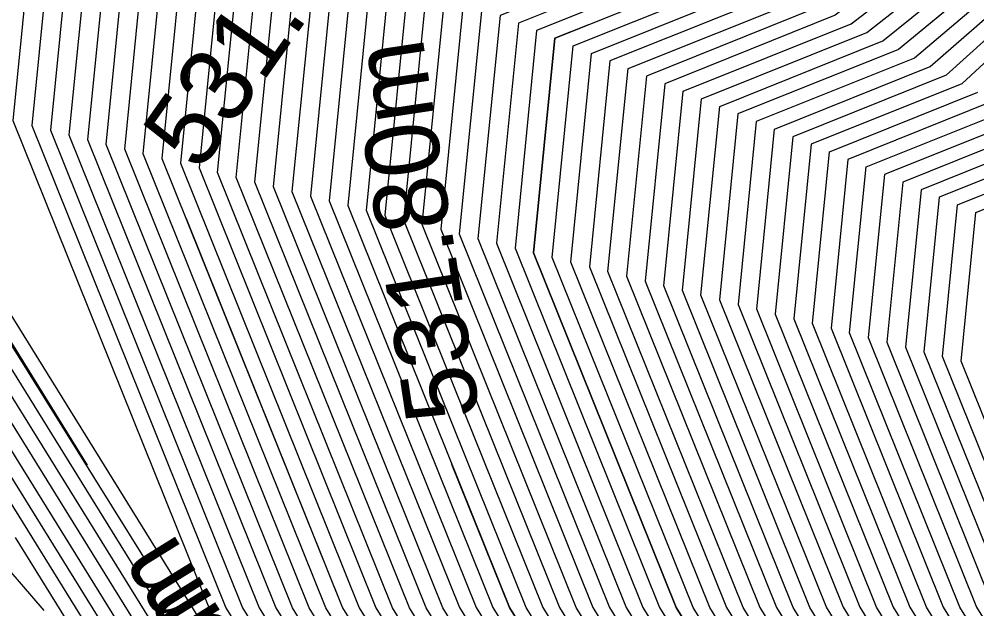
# Model space of a CAD drawing. Extents: x -866683 to -866410, y -1041951 to -1040252.
# Drawn here: x -866453.011 to -866449.115, y -1041913.65 to -1041911.251 of the extents above; entities that cross this region are included whole.
import ezdxf

# ---------------------------------------------------------------- set-up
doc = ezdxf.new("R2010")
doc.units = 0
for name, color, linetype in [('V-HL', 7, 'Continuous'), ('V-POPIS', 7, 'Continuous'), ('V-VEDL', 7, 'Continuous'), ('V_po_cm', 7, 'Continuous')]:
    doc.layers.add(name, color=color, linetype=linetype)

msp = doc.modelspace()

# ---------------------------------------------------------------- linework, layer by layer
at = {"layer": 'V-HL'}
msp.add_lwpolyline([(-866454.1336, -1041910.9392), (-866453.9375, -1041911.167), (-866453.3211, -1041912.1323), (-866452.4979, -1041913.4504)], dxfattribs=at)
at = {"layer": 'V-VEDL'}
for points in [[(-866449.345, -1041907.5366), (-866448.9556, -1041907.8532), (-866448.4862, -1041908.0339), (-866448.3105, -1041908.3809), (-866448.4285, -1041908.8942), (-866448.8402, -1041909.5738), (-866449.0019, -1041910.1655), (-866448.9134, -1041910.6692), (-866448.5749, -1041911.085), (-866448.5335, -1041911.4362), (-866448.7893, -1041911.7228), (-866449.3421, -1041911.9448), (-866449.4057, -1041912.585), (-866448.98, -1041913.6435), (-866448.0652, -1041915.1203), (-866447.345, -1041916.0757), (-866446.8195, -1041916.5099), (-866446.4887, -1041916.4228), (-866444.7099, -1041917.3864), (-866441.483, -1041919.4008), (-866432.1333, -1041925.5308)], [(-866449.0899, -1041915.6585), (-866450.3375, -1041913.6448), (-866450.9179, -1041912.2014), (-866450.8312, -1041911.3283), (-866450.0774, -1041911.0256), (-866449.6433, -1041910.7396), (-866449.529, -1041910.4704), (-866449.7345, -1041910.218), (-866449.7882, -1041909.9122), (-866449.69, -1041909.5531), (-866449.4401, -1041909.1405), (-866449.4048, -1041908.8149), (-866449.584, -1041908.5763), (-866449.9779, -1041908.4247), (-866450.6093, -1041908.3298), (-866451.4782, -1041908.2917), (-866452.5847, -1041908.3103), (-866453.3252, -1041908.3136), (-866453.6997, -1041908.3014), (-866453.7167, -1041908.2462)], [(-866452.8806, -1041908.7157), (-866451.3442, -1041908.6899), (-866450.7433, -1041908.7154), (-866450.3097, -1041908.7795), (-866450.0432, -1041908.882), (-866449.922, -1041909.0434), (-866449.9459, -1041909.2636), (-866450.1149, -1041909.5427), (-866450.1813, -1041909.7856), (-866450.145, -1041909.9925), (-866450.006, -1041910.1632), (-866450.1981, -1041910.3914), (-866450.7214, -1041910.677), (-866451.5758, -1041911.0201), (-866451.6741, -1041912.0096), (-866451.0162, -1041913.6454), (-866449.6023, -1041915.9277), (-866448.4893, -1041917.4043)], [(-866451.9822, -1041909.101), (-866451.181, -1041909.0875), (-866450.8676, -1041909.1009), (-866450.6414, -1041909.1343), (-866450.5025, -1041909.1878), (-866450.4392, -1041909.2719), (-866450.4517, -1041909.3868), (-866450.5399, -1041909.5323), (-866450.5745, -1041909.659), (-866450.5555, -1041909.7669), (-866450.483, -1041909.8559), (-866450.753, -1041910.0431), (-866451.3654, -1041910.3284), (-866452.3203, -1041910.7119), (-866452.4302, -1041911.8178), (-866451.695, -1041913.6461), (-866450.1147, -1041916.1968), (-866448.8707, -1041917.8472)], [(-866449.0884, -1041911.0879), (-866449.4333, -1041911.3742), (-866450.0867, -1041911.6366), (-866450.1618, -1041912.3932), (-866449.6588, -1041913.6442), (-866448.5775, -1041915.3894)]]:
    msp.add_lwpolyline(points, dxfattribs=at)
at = {"layer": 'V_po_cm'}
for points in [[(-866463.5642, -1041907.1206), (-866462.1303, -1041908.0993), (-866460.0158, -1041909.9324), (-866458.3918, -1041911.0851), (-866457.2584, -1041911.5573), (-866456.6155, -1041911.3489), (-866456.0661, -1041911.2348), (-866455.6103, -1041911.2147), (-866455.248, -1041911.2888), (-866454.787, -1041911.5932), (-866454.2273, -1041912.1278), (-866452.9104, -1041913.6573)], [(-866450.2492, -1041908.0307), (-866449.3085, -1041908.3929), (-866449.0944, -1041908.6778), (-866449.1366, -1041909.0666), (-866449.4351, -1041909.5593), (-866449.5523, -1041909.9882), (-866449.4882, -1041910.3534), (-866449.2428, -1041910.6548), (-866449.3104, -1041910.9486), (-866449.6909, -1041911.2348), (-866450.3845, -1041911.5133), (-866450.4643, -1041912.3165), (-866449.9303, -1041913.6444), (-866448.7825, -1041915.4971)], [(-866450.2696, -1041908.0711), (-866449.3544, -1041908.4234), (-866449.1462, -1041908.7006), (-866449.1872, -1041909.0789), (-866449.4776, -1041909.5582), (-866449.5916, -1041909.9755), (-866449.5292, -1041910.3308), (-866449.2905, -1041910.6241), (-866449.3658, -1041910.9138), (-866449.7553, -1041911.1999), (-866450.4589, -1041911.4824), (-866450.5399, -1041912.2973), (-866449.9981, -1041913.6445), (-866448.8337, -1041915.524)], [(-866448.885, -1041915.5509), (-866450.066, -1041913.6445), (-866450.6155, -1041912.2781), (-866450.5334, -1041911.4516), (-866449.8197, -1041911.165), (-866449.4213, -1041910.8789), (-866449.3382, -1041910.5934), (-866449.5703, -1041910.3083), (-866449.6309, -1041909.9629), (-866449.5201, -1041909.5572), (-866449.2378, -1041909.0912), (-866449.1979, -1041908.7235), (-866449.4004, -1041908.454), (-866450.2901, -1041908.1115)], [(-866450.3105, -1041908.1519), (-866449.4463, -1041908.4846), (-866449.2496, -1041908.7463), (-866449.2884, -1041909.1035), (-866449.5626, -1041909.5562), (-866449.6702, -1041909.9502), (-866449.6113, -1041910.2857), (-866449.3859, -1041910.5626), (-866449.4768, -1041910.8441), (-866449.8841, -1041911.1302), (-866450.6078, -1041911.4208), (-866450.6911, -1041912.2589), (-866450.1339, -1041913.6446), (-866448.9362, -1041915.5778)], [(-866448.9875, -1041915.6047), (-866450.2018, -1041913.6447), (-866450.7667, -1041912.2398), (-866450.6823, -1041911.39), (-866449.9485, -1041911.0953), (-866449.5323, -1041910.8093), (-866449.4336, -1041910.5319), (-866449.6524, -1041910.2631), (-866449.7095, -1041909.9376), (-866449.6051, -1041909.5551), (-866449.3389, -1041909.1159), (-866449.3013, -1041908.7692), (-866449.4922, -1041908.5151), (-866450.3309, -1041908.1923)], [(-866449.0387, -1041915.6316), (-866450.2696, -1041913.6447), (-866450.8423, -1041912.2206), (-866450.7568, -1041911.3592), (-866450.0129, -1041911.0605), (-866449.5878, -1041910.7745), (-866449.4813, -1041910.5012), (-866449.6934, -1041910.2406), (-866449.7489, -1041909.9249), (-866449.6476, -1041909.5541), (-866449.3895, -1041909.1282), (-866449.353, -1041908.792), (-866449.5381, -1041908.5457), (-866450.3514, -1041908.2327)], [(-866450.3922, -1041908.3134), (-866449.63, -1041908.6069), (-866449.4565, -1041908.8378), (-866449.4907, -1041909.1528), (-866449.7325, -1041909.552), (-866449.8275, -1041909.8996), (-866449.7755, -1041910.1955), (-866449.5767, -1041910.4397), (-866449.6988, -1041910.7048), (-866450.1418, -1041910.9907), (-866450.9057, -1041911.2975), (-866450.9935, -1041912.1822), (-866450.4054, -1041913.6449), (-866449.1412, -1041915.6855), (-866448.146, -1041917.0057)], [(-866450.4126, -1041908.3538), (-866449.6759, -1041908.6374), (-866449.5082, -1041908.8606), (-866449.5413, -1041909.1651), (-866449.775, -1041909.551), (-866449.8668, -1041909.8869), (-866449.8166, -1041910.1729), (-866449.6244, -1041910.409), (-866449.7542, -1041910.67), (-866450.2062, -1041910.9559), (-866450.9801, -1041911.2667), (-866451.0692, -1041912.163), (-866450.4733, -1041913.6449), (-866449.1924, -1041915.7124), (-866448.1841, -1041917.05)], [(-866450.4331, -1041908.3942), (-866449.7218, -1041908.668), (-866449.5599, -1041908.8835), (-866449.5918, -1041909.1774), (-866449.8175, -1041909.5499), (-866449.9061, -1041909.8743), (-866449.8576, -1041910.1504), (-866449.6721, -1041910.3783), (-866449.8097, -1041910.6352), (-866450.2706, -1041910.921), (-866451.0546, -1041911.2359), (-866451.1448, -1041912.1439), (-866450.5411, -1041913.645), (-866449.2436, -1041915.7393), (-866448.2223, -1041917.0943)], [(-866450.4535, -1041908.4346), (-866449.7677, -1041908.6986), (-866449.6117, -1041908.9063), (-866449.6424, -1041909.1897), (-866449.86, -1041909.5489), (-866449.9454, -1041909.8616), (-866449.8987, -1041910.1278), (-866449.7198, -1041910.3475), (-866449.8652, -1041910.6003), (-866450.335, -1041910.8862), (-866451.129, -1041911.205), (-866451.2204, -1041912.1247), (-866450.609, -1041913.6451), (-866449.2949, -1041915.7662), (-866448.2604, -1041917.1386)], [(-866450.4739, -1041908.475), (-866449.8136, -1041908.7292), (-866449.6634, -1041908.9292), (-866449.693, -1041909.2021), (-866449.9025, -1041909.5479), (-866449.9847, -1041909.8489), (-866449.9397, -1041910.1052), (-866449.7675, -1041910.3168), (-866449.9207, -1041910.5655), (-866450.3994, -1041910.8513), (-866451.2035, -1041911.1742), (-866451.296, -1041912.1055), (-866450.6769, -1041913.6451), (-866449.3461, -1041915.7931), (-866448.2986, -1041917.1829)], [(-866448.3367, -1041917.2272), (-866449.3974, -1041915.82), (-866450.7447, -1041913.6452), (-866451.3716, -1041912.0863), (-866451.278, -1041911.1434), (-866450.4638, -1041910.8164), (-866449.9762, -1041910.5307), (-866449.8152, -1041910.2861), (-866449.9808, -1041910.0827), (-866450.0241, -1041909.8363), (-866449.945, -1041909.5468), (-866449.7436, -1041909.2144), (-866449.7151, -1041908.952), (-866449.8596, -1041908.7597), (-866450.4944, -1041908.5154)], [(-866450.5148, -1041908.5558), (-866449.9055, -1041908.7903), (-866449.7668, -1041908.9749), (-866449.7942, -1041909.2267), (-866449.9875, -1041909.5458), (-866450.0634, -1041909.8236), (-866450.0219, -1041910.0601), (-866449.8629, -1041910.2554), (-866450.0317, -1041910.4958), (-866450.5282, -1041910.7816), (-866451.3524, -1041911.1126), (-866451.4472, -1041912.0671), (-866450.8126, -1041913.6453), (-866449.4486, -1041915.8469), (-866448.3749, -1041917.2714)], [(-866450.5352, -1041908.5961), (-866449.9514, -1041908.8209), (-866449.8185, -1041908.9977), (-866449.8447, -1041909.239), (-866450.03, -1041909.5448), (-866450.1027, -1041909.8109), (-866450.0629, -1041910.0376), (-866449.9106, -1041910.2246), (-866450.0872, -1041910.461), (-866450.5926, -1041910.7467), (-866451.4269, -1041911.0818), (-866451.5228, -1041912.048), (-866450.8805, -1041913.6453), (-866449.4998, -1041915.8738), (-866448.413, -1041917.3157)], [(-866448.4512, -1041917.36), (-866449.5511, -1041915.9008), (-866450.9484, -1041913.6454), (-866451.5984, -1041912.0288), (-866451.5013, -1041911.0509), (-866450.657, -1041910.7119), (-866450.1427, -1041910.4262), (-866449.9583, -1041910.1939), (-866450.104, -1041910.015), (-866450.142, -1041909.7983), (-866450.0725, -1041909.5437), (-866449.8953, -1041909.2513), (-866449.8703, -1041909.0206), (-866449.9973, -1041908.8515), (-866450.5556, -1041908.6365)], [(-866450.5965, -1041908.7173), (-866450.0892, -1041908.9126), (-866449.9737, -1041909.0663), (-866449.9965, -1041909.2759), (-866450.1574, -1041909.5416), (-866450.2206, -1041909.773), (-866450.1861, -1041909.9699), (-866450.0537, -1041910.1325), (-866450.2536, -1041910.3565), (-866450.7858, -1041910.6422), (-866451.6502, -1041910.9893), (-866451.7497, -1041911.9904), (-866451.0841, -1041913.6455), (-866449.6536, -1041915.9546), (-866448.5274, -1041917.4486)], [(-866450.6169, -1041908.7577), (-866450.1351, -1041908.9432), (-866450.0254, -1041909.0891), (-866450.0471, -1041909.2883), (-866450.1999, -1041909.5406), (-866450.2599, -1041909.7603), (-866450.2271, -1041909.9473), (-866450.1014, -1041910.1017), (-866450.3091, -1041910.3217), (-866450.8502, -1041910.6073), (-866451.7247, -1041910.9585), (-866451.8253, -1041911.9712), (-866451.152, -1041913.6456), (-866449.7048, -1041915.9815), (-866448.5656, -1041917.4929)], [(-866450.6373, -1041908.7981), (-866450.181, -1041908.9737), (-866450.0772, -1041909.112), (-866450.0976, -1041909.3006), (-866450.2424, -1041909.5396), (-866450.2993, -1041909.7476), (-866450.2682, -1041909.9248), (-866450.1491, -1041910.071), (-866450.3646, -1041910.2869), (-866450.9146, -1041910.5724), (-866451.7991, -1041910.9276), (-866451.9009, -1041911.952), (-866451.2199, -1041913.6456), (-866449.756, -1041916.0084), (-866448.6037, -1041917.5372)], [(-866448.6419, -1041917.5814), (-866449.8073, -1041916.0353), (-866451.2877, -1041913.6457), (-866451.9765, -1041911.9329), (-866451.8736, -1041910.8968), (-866450.979, -1041910.5376), (-866450.4201, -1041910.2521), (-866450.1968, -1041910.0403), (-866450.3092, -1041909.9022), (-866450.3386, -1041909.735), (-866450.2849, -1041909.5385), (-866450.1482, -1041909.3129), (-866450.1289, -1041909.1348), (-866450.2269, -1041909.0043), (-866450.6578, -1041908.8385)], [(-866448.68, -1041917.6257), (-866449.8585, -1041916.0622), (-866451.3556, -1041913.6458), (-866452.0521, -1041911.9137), (-866451.9481, -1041910.866), (-866451.0434, -1041910.5027), (-866450.4756, -1041910.2172), (-866450.2445, -1041910.0096), (-866450.3503, -1041909.8797), (-866450.3779, -1041909.7223), (-866450.3274, -1041909.5375), (-866450.1988, -1041909.3252), (-866450.1806, -1041909.1577), (-866450.2729, -1041909.0349), (-866450.6782, -1041908.8788)], [(-866448.7182, -1041917.67), (-866449.9098, -1041916.0892), (-866451.4235, -1041913.6458), (-866452.1277, -1041911.8945), (-866452.0225, -1041910.8352), (-866451.1078, -1041910.4679), (-866450.5311, -1041910.1824), (-866450.2922, -1041909.9788), (-866450.3913, -1041909.8571), (-866450.4172, -1041909.7097), (-866450.3699, -1041909.5365), (-866450.2494, -1041909.3375), (-866450.2323, -1041909.1805), (-866450.3188, -1041909.0655), (-866450.6986, -1041908.9192)], [(-866448.7563, -1041917.7143), (-866449.961, -1041916.1161), (-866451.4914, -1041913.6459), (-866452.2033, -1041911.8753), (-866452.097, -1041910.8044), (-866451.1722, -1041910.433), (-866450.5866, -1041910.1476), (-866450.3399, -1041909.9481), (-866450.4324, -1041909.8346), (-866450.4565, -1041909.697), (-866450.4124, -1041909.5354), (-866450.2999, -1041909.3498), (-866450.2841, -1041909.2034), (-866450.3647, -1041909.096), (-866450.7191, -1041908.9596)], [(-866450.7395, -1041909), (-866450.4106, -1041909.1266), (-866450.3358, -1041909.2262), (-866450.3505, -1041909.3621), (-866450.4549, -1041909.5344), (-866450.4958, -1041909.6843), (-866450.4734, -1041909.812), (-866450.3876, -1041909.9174), (-866450.642, -1041910.1128), (-866451.2366, -1041910.3981), (-866452.1714, -1041910.7735), (-866452.279, -1041911.8561), (-866451.5592, -1041913.646), (-866450.0122, -1041916.143), (-866448.7945, -1041917.7586)], [(-866450.7599, -1041909.0404), (-866450.4565, -1041909.1572), (-866450.3875, -1041909.2491), (-866450.4011, -1041909.3745), (-866450.4974, -1041909.5333), (-866450.5352, -1041909.6717), (-866450.5145, -1041909.7894), (-866450.4353, -1041909.8866), (-866450.6975, -1041910.0779), (-866451.301, -1041910.3633), (-866452.2459, -1041910.7427), (-866452.3546, -1041911.837), (-866451.6271, -1041913.646), (-866450.0635, -1041916.1699), (-866448.8326, -1041917.8029)], [(-866448.68, -1041915.4432), (-866449.7945, -1041913.6443), (-866450.313, -1041912.3549), (-866450.2356, -1041911.5749), (-866449.5621, -1041911.3045), (-866449.1994, -1041911.0182), (-866449.1474, -1041910.7163), (-866449.4061, -1041910.3985), (-866449.4737, -1041910.0135), (-866449.3501, -1041909.5614), (-866449.0355, -1041909.042)], [(-866448.6288, -1041915.4163), (-866449.7266, -1041913.6442), (-866450.2374, -1041912.374), (-866450.1611, -1041911.6057), (-866449.4977, -1041911.3393), (-866449.1439, -1041911.0531), (-866449.0997, -1041910.747), (-866449.365, -1041910.4211), (-866449.4343, -1041910.0262), (-866449.3076, -1041909.5624), (-866448.9849, -1041909.0297)], [(-866448.7313, -1041915.4701), (-866449.8624, -1041913.6444), (-866450.3886, -1041912.3357), (-866450.31, -1041911.5441), (-866449.6265, -1041911.2696), (-866449.2549, -1041910.9834), (-866449.1951, -1041910.6855), (-866449.4471, -1041910.3759), (-866449.513, -1041910.0009), (-866449.3926, -1041909.5603), (-866449.086, -1041909.0543)], [(-866448.9089, -1041917.8914), (-866450.166, -1041916.2237), (-866451.7628, -1041913.6461), (-866452.5058, -1041911.7986), (-866452.3948, -1041910.6811), (-866451.4298, -1041910.2936), (-866450.8085, -1041910.0083), (-866450.5307, -1041909.8252), (-866450.5966, -1041909.7443), (-866450.6138, -1041909.6463), (-866450.5823, -1041909.5313), (-866450.5023, -1041909.3991), (-866450.4909, -1041909.2948), (-866450.5484, -1041909.2183), (-866450.8008, -1041909.1212)], [(-866448.947, -1041917.9357), (-866450.2172, -1041916.2506), (-866451.8307, -1041913.6462), (-866452.5814, -1041911.7794), (-866452.4693, -1041910.6502), (-866451.4943, -1041910.2587), (-866450.864, -1041909.9734), (-866450.5784, -1041909.7945), (-866450.6376, -1041909.7218), (-866450.6531, -1041909.6337), (-866450.6248, -1041909.5302), (-866450.5528, -1041909.4114), (-866450.5427, -1041909.3176), (-866450.5943, -1041909.2489), (-866450.8212, -1041909.1616)], [(-866448.9852, -1041917.98), (-866450.2684, -1041916.2776), (-866451.8986, -1041913.6463), (-866452.657, -1041911.7602), (-866452.5437, -1041910.6194), (-866451.5587, -1041910.2238), (-866450.9195, -1041909.9386), (-866450.6261, -1041909.7637), (-866450.6787, -1041909.6992), (-866450.6924, -1041909.621), (-866450.6673, -1041909.5292), (-866450.6034, -1041909.4237), (-866450.5944, -1041909.3405), (-866450.6402, -1041909.2795), (-866450.8416, -1041909.2019)], [(-866450.862, -1041909.2423), (-866450.6861, -1041909.31), (-866450.6461, -1041909.3633), (-866450.654, -1041909.436), (-866450.7098, -1041909.5282), (-866450.7317, -1041909.6084), (-866450.7197, -1041909.6766), (-866450.6739, -1041909.733), (-866450.975, -1041909.9038), (-866451.6231, -1041910.189), (-866452.6182, -1041910.5886), (-866452.7326, -1041911.7411), (-866451.9665, -1041913.6463), (-866450.3197, -1041916.3045), (-866449.0233, -1041918.0243)], [(-866450.8825, -1041909.2827), (-866450.7321, -1041909.3406), (-866450.6978, -1041909.3862), (-866450.7046, -1041909.4483), (-866450.7523, -1041909.5271), (-866450.771, -1041909.5957), (-866450.7608, -1041909.6541), (-866450.7216, -1041909.7023), (-866451.0304, -1041909.869), (-866451.6875, -1041910.1541), (-866452.6926, -1041910.5578), (-866452.8082, -1041911.7219), (-866452.0343, -1041913.6464), (-866450.3709, -1041916.3314), (-866449.0615, -1041918.0686)], [(-866450.9029, -1041909.3231), (-866450.778, -1041909.3712), (-866450.7496, -1041909.409), (-866450.7552, -1041909.4607), (-866450.7948, -1041909.5261), (-866450.8104, -1041909.583), (-866450.8018, -1041909.6315), (-866450.7693, -1041909.6716), (-866451.0859, -1041909.8341), (-866451.7519, -1041910.1193), (-866452.7671, -1041910.527), (-866452.8839, -1041911.7027), (-866452.1022, -1041913.6465), (-866450.4221, -1041916.3583), (-866449.0996, -1041918.1129)], [(-866450.9233, -1041909.3635), (-866450.8239, -1041909.4018), (-866450.8013, -1041909.4319), (-866450.8057, -1041909.473), (-866450.8373, -1041909.525), (-866450.8497, -1041909.5704), (-866450.8429, -1041909.609), (-866450.817, -1041909.6408), (-866451.1414, -1041909.7993), (-866451.8163, -1041910.0844), (-866452.8415, -1041910.4961), (-866452.9595, -1041911.6835), (-866452.1701, -1041913.6465), (-866450.4734, -1041916.3852), (-866449.1378, -1041918.1572), (-866448.1632, -1041918.9624)], [(-866448.1918, -1041919.0146), (-866449.1759, -1041918.2014), (-866450.5246, -1041916.4121), (-866452.238, -1041913.6466), (-866453.0351, -1041911.6643), (-866452.916, -1041910.4653), (-866451.8807, -1041910.0496), (-866451.1969, -1041909.7645), (-866450.8647, -1041909.6101), (-866450.8839, -1041909.5864), (-866450.889, -1041909.5577), (-866450.8798, -1041909.524), (-866450.8563, -1041909.4853), (-866450.853, -1041909.4547), (-866450.8698, -1041909.4323), (-866450.9438, -1041909.4039)], [(-866453.9556, -1041910.9838), (-866450.5491, -1041916.4822), (-866449.2051, -1041918.2601), (-866448.2204, -1041919.0667), (-866447.5949, -1041918.902), (-866445.7626, -1041919.7202), (-866442.7235, -1041921.5211), (-866438.4776, -1041924.3049), (-866435.6682, -1041926.3451), (-866434.2952, -1041927.6416), (-866434.3586, -1041928.1946), (-866434.3894, -1041928.6198), (-866434.3877, -1041928.9172), (-866434.3533, -1041929.0867), (-866434.5515, -1041929.5677), (-866434.9823, -1041930.3602), (-866436.3089, -1041932.5679)], [(-866449.0329, -1041911.1227), (-866449.3689, -1041911.409), (-866450.0122, -1041911.6674), (-866450.0862, -1041912.4124), (-866449.5909, -1041913.6441), (-866448.5263, -1041915.3625)], [(-866449.1897, -1041911.172), (-866449.4333, -1041911.3742), (-866450.0867, -1041911.6366), (-866450.1618, -1041912.3932), (-866449.6588, -1041913.6442), (-866449.1812, -1041914.4151)], [(-866448.4751, -1041915.3356), (-866449.523, -1041913.644), (-866450.0106, -1041912.4316), (-866449.9377, -1041911.6982), (-866449.3045, -1041911.4439), (-866448.9774, -1041911.1576)], [(-866448.9219, -1041911.1924), (-866449.2401, -1041911.4788), (-866449.8633, -1041911.729), (-866449.935, -1041912.4508), (-866449.4552, -1041913.644), (-866448.4238, -1041915.3087)], [(-866448.8665, -1041911.2272), (-866449.1757, -1041911.5136), (-866449.7888, -1041911.7598), (-866449.8594, -1041912.4699), (-866449.3873, -1041913.6439), (-866448.3726, -1041915.2817)], [(-866453.8394, -1041911.2809), (-866452.7335, -1041913.066)], [(-866450.6946, -1041911.2735), (-866450.8312, -1041911.3283), (-866450.9179, -1041912.2014), (-866450.3375, -1041913.6448), (-866449.6105, -1041914.8183)], [(-866448.5527, -1041911.274), (-866448.5335, -1041911.4362), (-866448.7893, -1041911.7228), (-866449.3421, -1041911.9448), (-866449.4057, -1041912.585), (-866448.98, -1041913.6435), (-866448.3706, -1041914.6272)], [(-866453.7233, -1041911.5779), (-866450.5178, -1041916.7519), (-866449.2368, -1041918.4207), (-866448.2776, -1041919.1711), (-866447.64, -1041919.0032), (-866445.8179, -1041919.8073), (-866442.8113, -1041921.5833), (-866438.6201, -1041924.3313), (-866435.8481, -1041926.3566), (-866434.4954, -1041927.6592), (-866434.5619, -1041928.2392), (-866434.5942, -1041928.6852), (-866434.5924, -1041928.9971), (-866434.5563, -1041929.175), (-866434.7642, -1041929.6795), (-866435.216, -1041930.5107), (-866436.6075, -1041932.8263)], [(-866448.3213, -1041915.2548), (-866449.3194, -1041913.6438), (-866449.7837, -1041912.4891), (-866449.7144, -1041911.7907), (-866449.1113, -1041911.5485)], [(-866449.0469, -1041911.5833), (-866449.6399, -1041911.8215), (-866449.7081, -1041912.5083), (-866449.2515, -1041913.6438), (-866448.2701, -1041915.2279)], [(-866448.2189, -1041915.201), (-866449.1837, -1041913.6437), (-866449.6325, -1041912.5275), (-866449.5655, -1041911.8523), (-866448.9825, -1041911.6182)], [(-866448.9181, -1041911.6531), (-866449.491, -1041911.8831), (-866449.5569, -1041912.5467), (-866449.1158, -1041913.6437), (-866448.1676, -1041915.1741)], [(-866448.8537, -1041911.6879), (-866449.4165, -1041911.914), (-866449.4813, -1041912.5658), (-866449.0479, -1041913.6436)], [(-866448.7249, -1041911.7576), (-866449.2676, -1041911.9756), (-866449.3301, -1041912.6042), (-866448.9122, -1041913.6435)], [(-866448.8443, -1041913.6434), (-866449.2545, -1041912.6234), (-866449.1932, -1041912.0064), (-866448.6604, -1041911.7925)], [(-866448.7764, -1041913.6433), (-866449.1788, -1041912.6426), (-866449.1187, -1041912.0372), (-866448.596, -1041911.8273)], [(-866453.6072, -1041911.875), (-866450.5022, -1041916.8868), (-866449.2527, -1041918.5009), (-866448.3062, -1041919.2233), (-866447.6626, -1041919.0538), (-866445.8456, -1041919.8509), (-866442.8552, -1041921.6144), (-866438.6913, -1041924.3444), (-866435.938, -1041926.3623), (-866434.5954, -1041927.668), (-866434.6635, -1041928.2615), (-866434.6966, -1041928.7179), (-866434.6947, -1041929.0371), (-866434.6578, -1041929.2191), (-866434.8706, -1041929.7354), (-866435.3329, -1041930.586), (-866436.7568, -1041932.9556)], [(-866452.3317, -1041912.0626), (-866451.695, -1041913.6461), (-866450.5156, -1041915.5497)], [(-866453.4911, -1041912.172), (-866450.4866, -1041917.0217), (-866449.2685, -1041918.5812), (-866448.3348, -1041919.2755), (-866447.6852, -1041919.1044), (-866445.8733, -1041919.8945), (-866442.899, -1041921.6455), (-866438.7625, -1041924.3576), (-866436.028, -1041926.3681), (-866434.6955, -1041927.6768), (-866434.7651, -1041928.2839), (-866434.799, -1041928.7506), (-866434.797, -1041929.0771), (-866434.7593, -1041929.2632), (-866434.9769, -1041929.7913), (-866435.4498, -1041930.6612), (-866436.9061, -1041933.0848)], [(-866437.0554, -1041933.2141), (-866435.5667, -1041930.7365), (-866435.0833, -1041929.8472), (-866434.8608, -1041929.3074), (-866434.8994, -1041929.1171), (-866434.9014, -1041928.7833), (-866434.8668, -1041928.3062), (-866434.7956, -1041927.6856), (-866436.1179, -1041926.3738), (-866438.8337, -1041924.3708), (-866442.9429, -1041921.6766), (-866445.901, -1041919.938), (-866447.7078, -1041919.155), (-866448.3633, -1041919.3276), (-866449.2844, -1041918.6615), (-866450.4709, -1041917.1565), (-866453.3749, -1041912.4691)], [(-866437.2047, -1041933.3433), (-866435.6835, -1041930.8117), (-866435.1896, -1041929.9031), (-866434.9623, -1041929.3515), (-866435.0017, -1041929.157), (-866435.0037, -1041928.816), (-866434.9684, -1041928.3285), (-866434.8957, -1041927.6944), (-866436.2078, -1041926.3796), (-866438.9049, -1041924.384), (-866442.9868, -1041921.7077), (-866445.9286, -1041919.9816), (-866447.7303, -1041919.2056), (-866448.3919, -1041919.3798), (-866449.3002, -1041918.7417), (-866450.4553, -1041917.2914), (-866453.2588, -1041912.7662)], [(-866437.354, -1041933.4725), (-866435.8004, -1041930.887), (-866435.296, -1041929.959), (-866435.0638, -1041929.3956), (-866435.1041, -1041929.197), (-866435.1061, -1041928.8487), (-866435.07, -1041928.3508), (-866434.9958, -1041927.7032), (-866436.2978, -1041926.3853), (-866438.9761, -1041924.3972), (-866443.0307, -1041921.7388), (-866445.9563, -1041920.0252), (-866447.7529, -1041919.2562), (-866448.4205, -1041919.432), (-866449.3161, -1041918.822), (-866450.4397, -1041917.4262), (-866453.1427, -1041913.0632)], [(-866449.0952, -1041916.6004), (-866449.6023, -1041915.9277), (-866451.0162, -1041913.6454), (-866451.2502, -1041913.0635)], [(-866453.0266, -1041913.3603), (-866450.424, -1041917.5611), (-866449.332, -1041918.9023), (-866448.4491, -1041919.4842), (-866447.7755, -1041919.3068), (-866445.984, -1041920.0687), (-866443.0746, -1041921.7699), (-866439.0473, -1041924.4104), (-866436.3877, -1041926.3911), (-866435.0958, -1041927.712), (-866435.1717, -1041928.3731), (-866435.2085, -1041928.8815), (-866435.2064, -1041929.237), (-866435.1653, -1041929.4398), (-866435.4023, -1041930.0148), (-866435.9173, -1041930.9623), (-866437.5033, -1041933.6018)]]:
    msp.add_lwpolyline(points, dxfattribs=at)

# ---------------------------------------------------------------- texts
at = {"layer": 'V-POPIS'}
msp.add_text('532m', height=0.3, rotation=121.8817, dxfattribs=at).set_placement((-866451.762, -1041914.3494))
at = {"layer": 'V_po_cm'}
for s, rotation, p in [('531.90m', 54.9989, (-866452.2782, -1041911.8791)), ('531.80m', 98.6432, (-866451.1359, -1041912.8631)), ('532.00m', 121.7796, (-866451.5684, -1041914.6617))]:
    msp.add_text(s, height=0.3, rotation=rotation, dxfattribs=at).set_placement(p)

doc.saveas('drawing.dxf')
